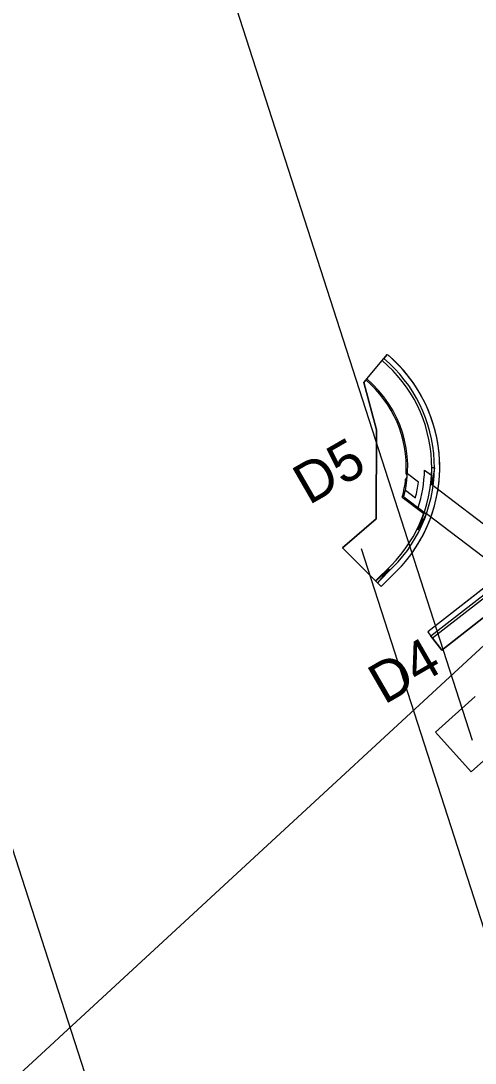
# Model space of a CAD drawing. Extents: x -759005 to -757278, y -1175311 to -1173953.
# Drawn here: x -758451.1 to -758425.6, y -1174861 to -1174802.3 of the extents above; entities that cross this region are included whole.
import ezdxf

# ---------------------------------------------------------------- set-up
doc = ezdxf.new("R2010")
doc.units = 0
for name, color, linetype in [('__NOR-dočasný zábor', 7, 'Continuous'), ('_NOR-návrh silná', 7, 'Continuous'), ('_NOR-návrh tenká', 7, 'Continuous'), ('_NOR-popis', 7, 'Continuous'), ('G_Obvod stavby', 7, 'Continuous'), ('KOS_PZZ nové', 7, 'Continuous')]:
    doc.layers.add(name, color=color, linetype=linetype)

msp = doc.modelspace()

# ---------------------------------------------------------------- linework, layer by layer
at = {"layer": '__NOR-dočasný zábor'}
for p, q in [((-758431.833, -1174822.623), (-758430.506, -1174821.051)), ((-758431.12, -1174825.29), (-758431.833, -1174822.623)), ((-758431.14, -1174830.31), (-758431.12, -1174825.29)), ((-758433.036, -1174831.952), (-758431.14, -1174830.31)), ((-758431.169, -1174833.809), (-758433.036, -1174831.952)), ((-758431.063, -1174833.915), (-758431.169, -1174833.809)), ((-758429.975, -1174833.247), (-758430.85, -1174834.126)), ((-758430.85, -1174834.126), (-758431.063, -1174833.915)), ((-758425.144, -1174834.274), (-758428.234, -1174836.675)), ((-758428.234, -1174836.675), (-758428.05, -1174836.912)), ((-758428.05, -1174836.912), (-758427.958, -1174837.03))]:
    msp.add_line(p, q, dxfattribs=at)
msp.add_lwpolyline([(-758427.958, -1174837.03), (-758427.436, -1174837.702), (-758424.916, -1174835.743)], dxfattribs=at)
for start, end in [(341.63709, 49.8317), (315.14993, 341.63709)]:
    msp.add_arc((-758435.859, -1174827.393), 8.3, start, end, dxfattribs=at)
at = {"layer": '_NOR-návrh silná'}
msp.add_line((-758430.188, -1174833.035), (-758431.063, -1174833.915), dxfattribs=at)
for points in [[(-758429.577, -1174829.063), (-758428.432, -1174829.935)], [(-758424.891, -1174834.458), (-758428.05, -1174836.912)]]:
    msp.add_lwpolyline(points, dxfattribs=at)
for radius, start in [(8, 315.14993), (6.5, 345.11722)]:
    msp.add_arc((-758435.859, -1174827.393), radius, start, 49.8317, dxfattribs=at)
at = {"layer": '_NOR-návrh tenká'}
for p, q in [((-758431.667, -1174822.426), (-758430.699, -1174821.28)), ((-758431.718, -1174822.487), (-758431.667, -1174822.426)), ((-758427.86, -1174827.437), (-758428.01, -1174827.437)), ((-758427.996, -1174828.382), (-758428.01, -1174827.437)), ((-758427.86, -1174827.437), (-758427.996, -1174828.382)), ((-758428.065, -1174828.329), (-758427.927, -1174828.434)), ((-758427.927, -1174828.434), (-758421.919, -1174833.013)), ((-758429.228, -1174829.329), (-758429.276, -1174829.393)), ((-758428.46, -1174830.015), (-758429.252, -1174829.361)), ((-758429.252, -1174829.361), (-758428.432, -1174829.935)), ((-758428.46, -1174830.015), (-758428.762, -1174830.918)), ((-758428.762, -1174830.918), (-758428.307, -1174830.031)), ((-758428.432, -1174829.935), (-758428.307, -1174830.031)), ((-758423.583, -1174833.631), (-758428.307, -1174830.031)), ((-758428.694, -1174830.952), (-758428.829, -1174830.885)), ((-758430.294, -1174832.929), (-758431.169, -1174833.809)), ((-758431.169, -1174833.809), (-758430.411, -1174833.153)), ((-758430.411, -1174833.153), (-758431.063, -1174833.915)), ((-758430.464, -1174833.1), (-758430.358, -1174833.206)), ((-758431.169, -1174833.809), (-758431.063, -1174833.915))]:
    msp.add_line(p, q, dxfattribs=at)
for points in [[(-758430.506, -1174821.051), (-758430.699, -1174821.28)], [(-758431.718, -1174822.487), (-758431.833, -1174822.623), (-758431.12, -1174825.29), (-758431.14, -1174830.31), (-758433.036, -1174831.952), (-758431.169, -1174833.809)], [(-758428.76, -1174828.24), (-758429.371, -1174827.774)], [(-758428.411, -1174827.562), (-758428.023, -1174827.858)], [(-758429.669, -1174829.094), (-758428.46, -1174830.015)], [(-758429.49, -1174828.689), (-758428.922, -1174829.122)], [(-758431.063, -1174833.915), (-758430.85, -1174834.126), (-758429.975, -1174833.247)], [(-758425.075, -1174834.221), (-758428.234, -1174836.675), (-758428.05, -1174836.912)], [(-758424.799, -1174834.576), (-758427.958, -1174837.03), (-758428.05, -1174836.912)], [(-758424.916, -1174835.743), (-758427.436, -1174837.702), (-758427.958, -1174837.03)]]:
    msp.add_lwpolyline(points, dxfattribs=at)
for centre, radius, start, end in [((-758435.859, -1174827.393), 7.85, 315.14993, 49.8317), ((-758435.859, -1174827.393), 8.3, 315.14993, 49.8317), ((-758435.859, -1174827.393), 6.42, 356.62812, 49.8317), ((-758429.595, -1174827.909), 0.2, 306.83758, 43.74665), ((-758435.859, -1174827.393), 7.45, 342.13228, 358.69772), ((-758435.859, -1174827.393), 6.42, 344.64034, 353.95611), ((-758435.859, -1174827.393), 7.15, 346.00437, 353.19845)]:
    msp.add_arc(centre, radius, start, end, dxfattribs=at)
at = {"layer": '_NOR-popis'}
for points in [[(-758436.507, -1174778.308), (-758445.549, -1174781.221), (-758425.724, -1174842.771)], [(-758460.521, -1174790.246), (-758469.563, -1174793.158), (-758441.828, -1174879.266)], [(-758421.971, -1174894), (-758412.929, -1174891.088), (-758431.963, -1174831.996)]]:
    msp.add_lwpolyline(points, dxfattribs=at)
at = {"layer": 'G_Obvod stavby'}
for p, q in [((-758431.833, -1174822.623), (-758430.506, -1174821.051)), ((-758431.12, -1174825.29), (-758431.833, -1174822.623)), ((-758431.14, -1174830.31), (-758431.12, -1174825.29)), ((-758433.036, -1174831.952), (-758431.14, -1174830.31)), ((-758431.169, -1174833.809), (-758433.036, -1174831.952)), ((-758431.063, -1174833.915), (-758431.169, -1174833.809)), ((-758429.975, -1174833.247), (-758430.85, -1174834.126)), ((-758430.85, -1174834.126), (-758431.063, -1174833.915)), ((-758425.144, -1174834.274), (-758428.234, -1174836.675)), ((-758428.234, -1174836.675), (-758428.05, -1174836.912)), ((-758428.05, -1174836.912), (-758427.958, -1174837.03))]:
    msp.add_line(p, q, dxfattribs=at)
for points in [[(-758424.368, -1174835.441), (-758423.81, -1174836.28), (-758457.56, -1174867.46)], [(-758427.958, -1174837.03), (-758427.436, -1174837.702), (-758424.916, -1174835.743)]]:
    msp.add_lwpolyline(points, dxfattribs=at)
for start, end in [(341.63709, 49.8317), (315.14993, 341.63709)]:
    msp.add_arc((-758435.859, -1174827.393), 8.3, start, end, dxfattribs=at)
at = {"layer": 'KOS_PZZ nové'}
for p, q in [((-758425.565, -1174840.327), (-758427.794, -1174842.335)), ((-758427.794, -1174842.335), (-758425.786, -1174844.564)), ((-758425.786, -1174844.564), (-758423.557, -1174842.556))]:
    msp.add_line(p, q, dxfattribs=at)

# ---------------------------------------------------------------- texts
at = {"layer": '__NOR-dočasný zábor'}
for s, p in [('D5', (-758434.918, -1174829.559)), ('D4', (-758430.679, -1174840.801))]:
    msp.add_text(s, height=2.2727, rotation=30, dxfattribs=at).set_placement(p)

doc.saveas('drawing.dxf')
